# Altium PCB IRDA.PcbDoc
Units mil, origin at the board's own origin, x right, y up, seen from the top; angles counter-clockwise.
Board outline 3020 x 2198 mil, 4 copper layers (Top Layer, PwrPlane, GndPlane, Bottom Layer); 52 components, 34 nets, 373 pads, 123 vias.
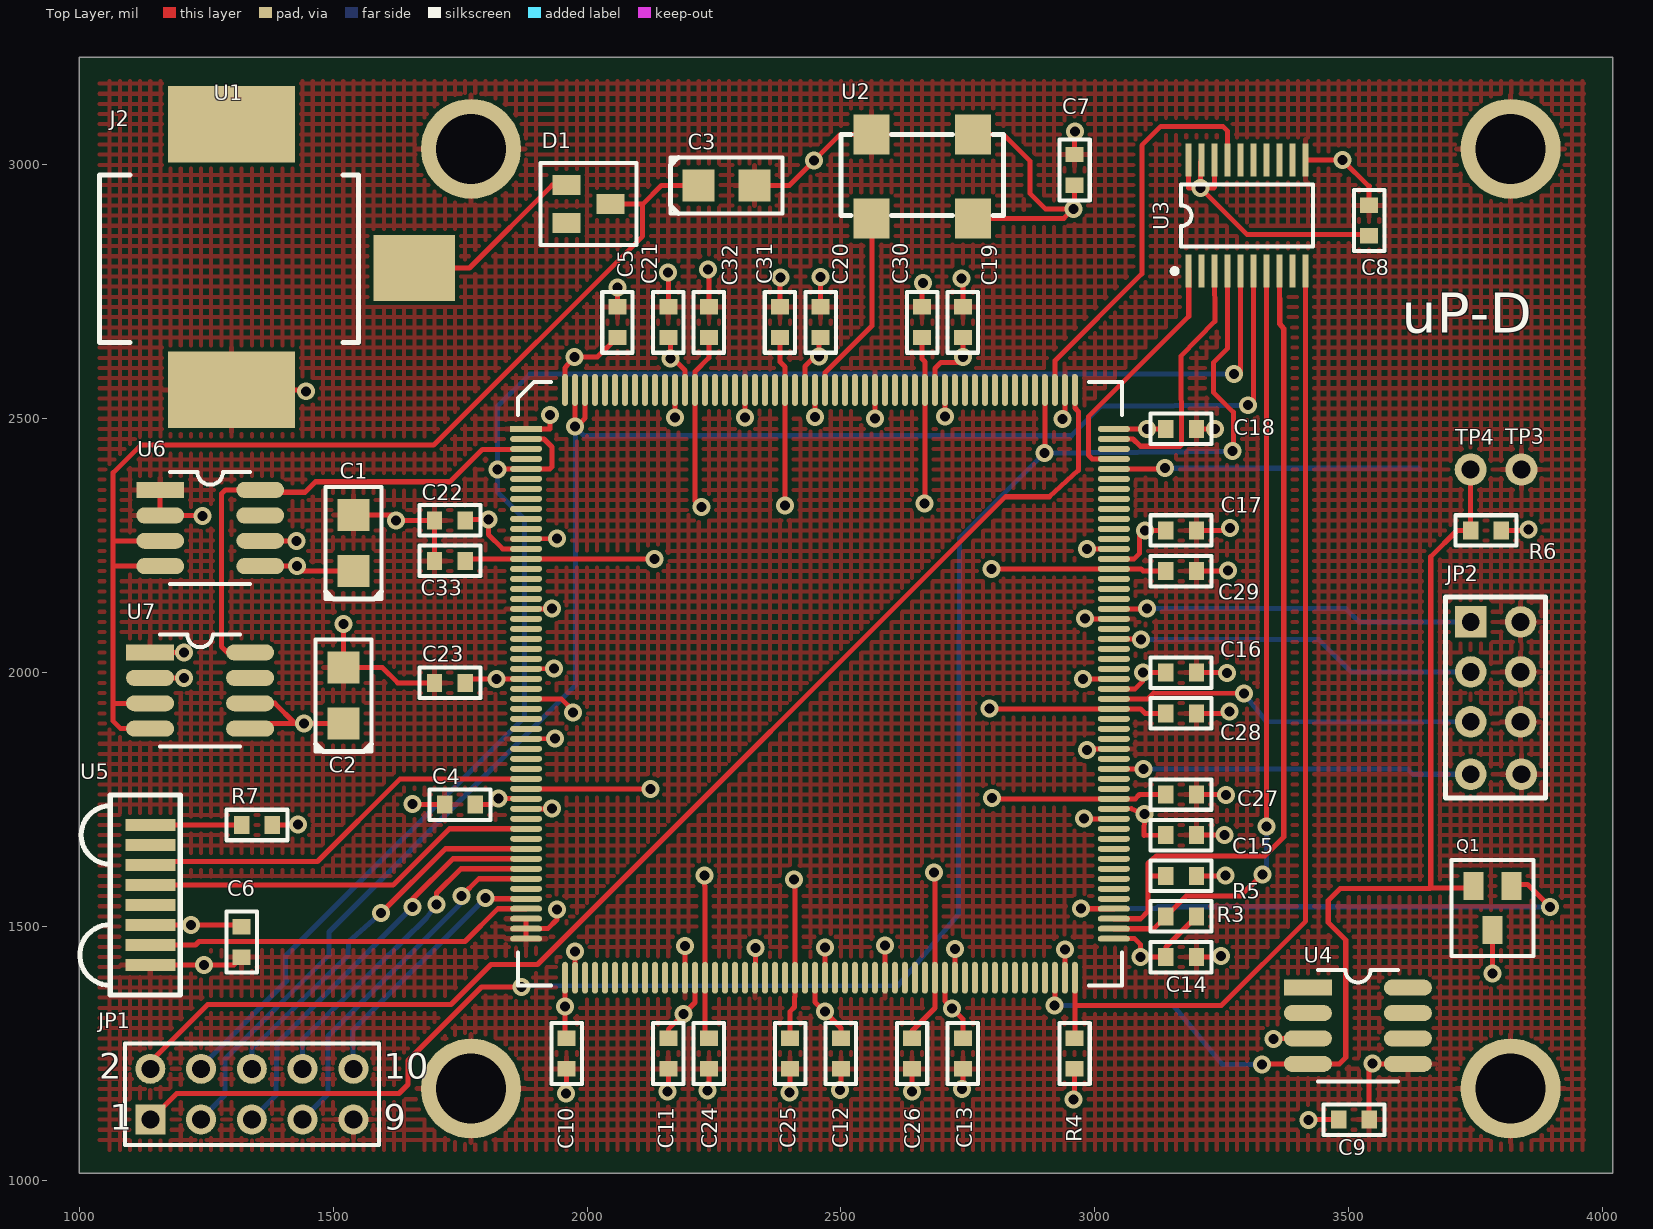
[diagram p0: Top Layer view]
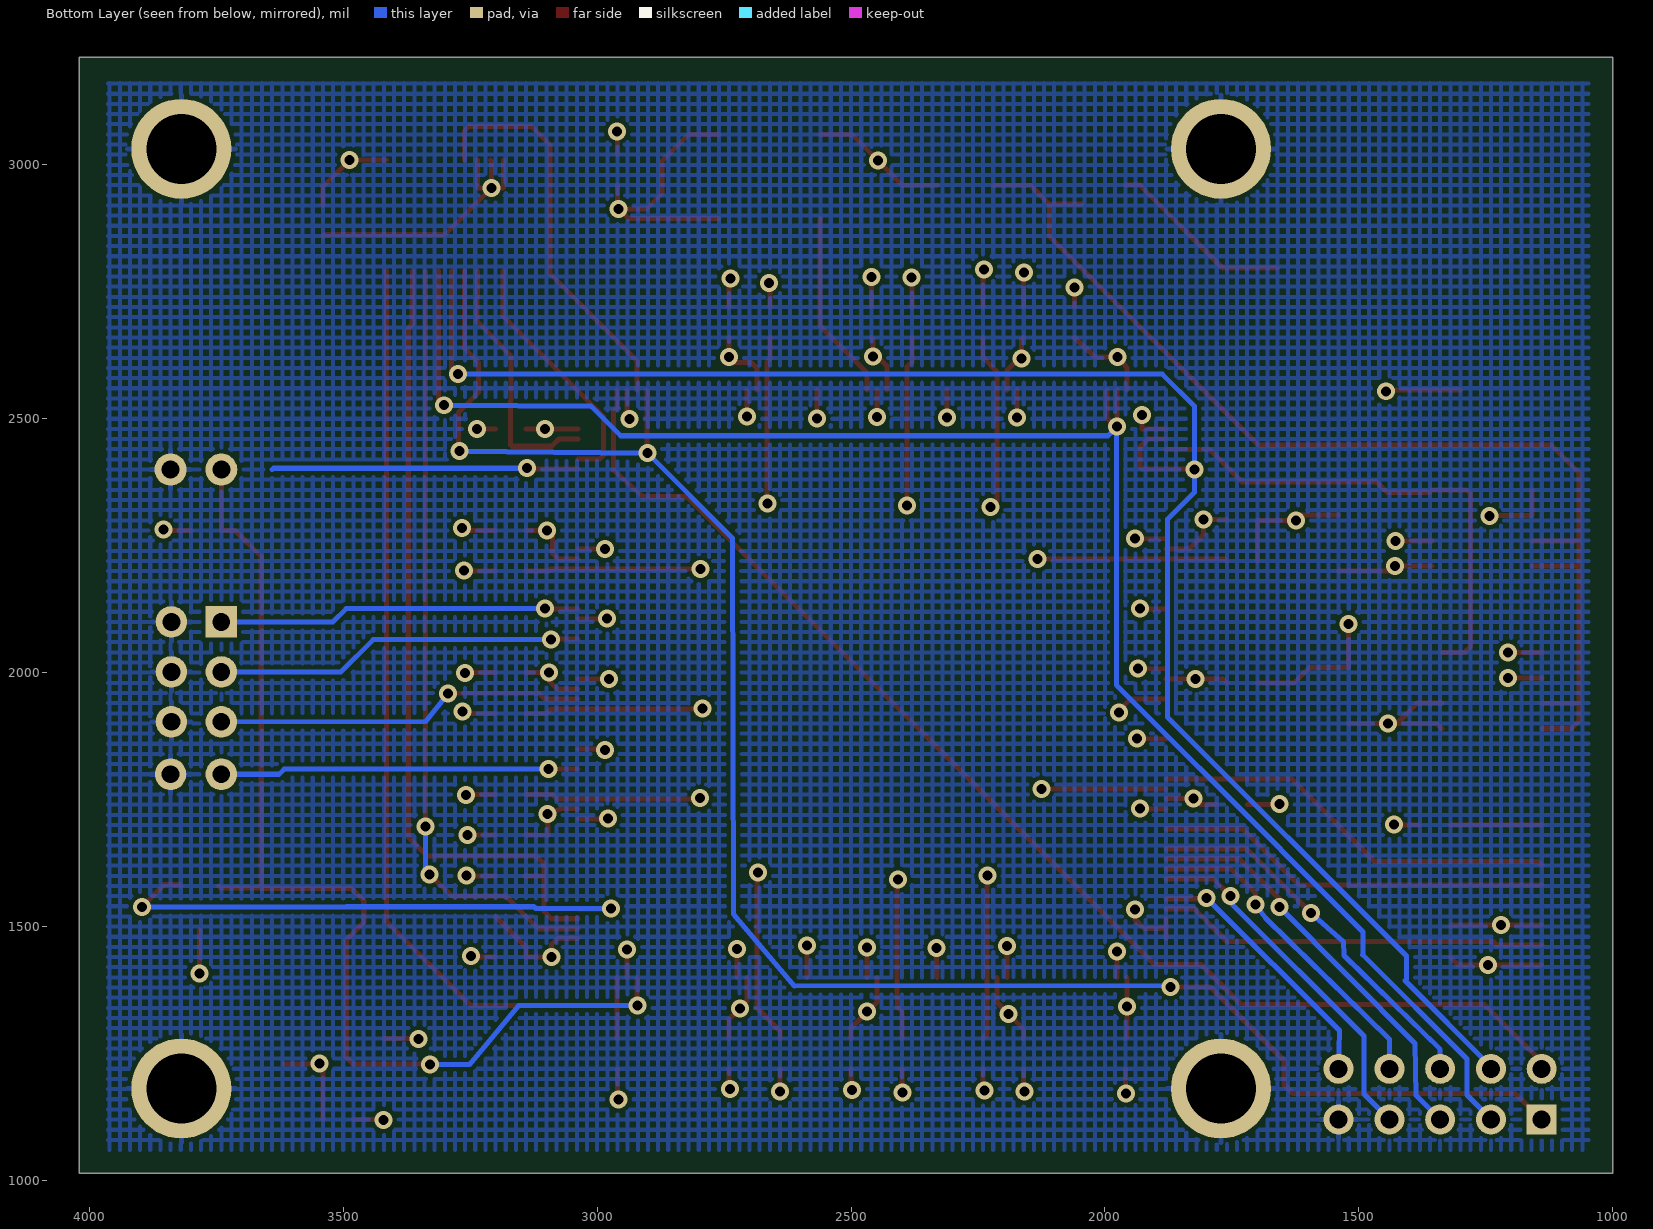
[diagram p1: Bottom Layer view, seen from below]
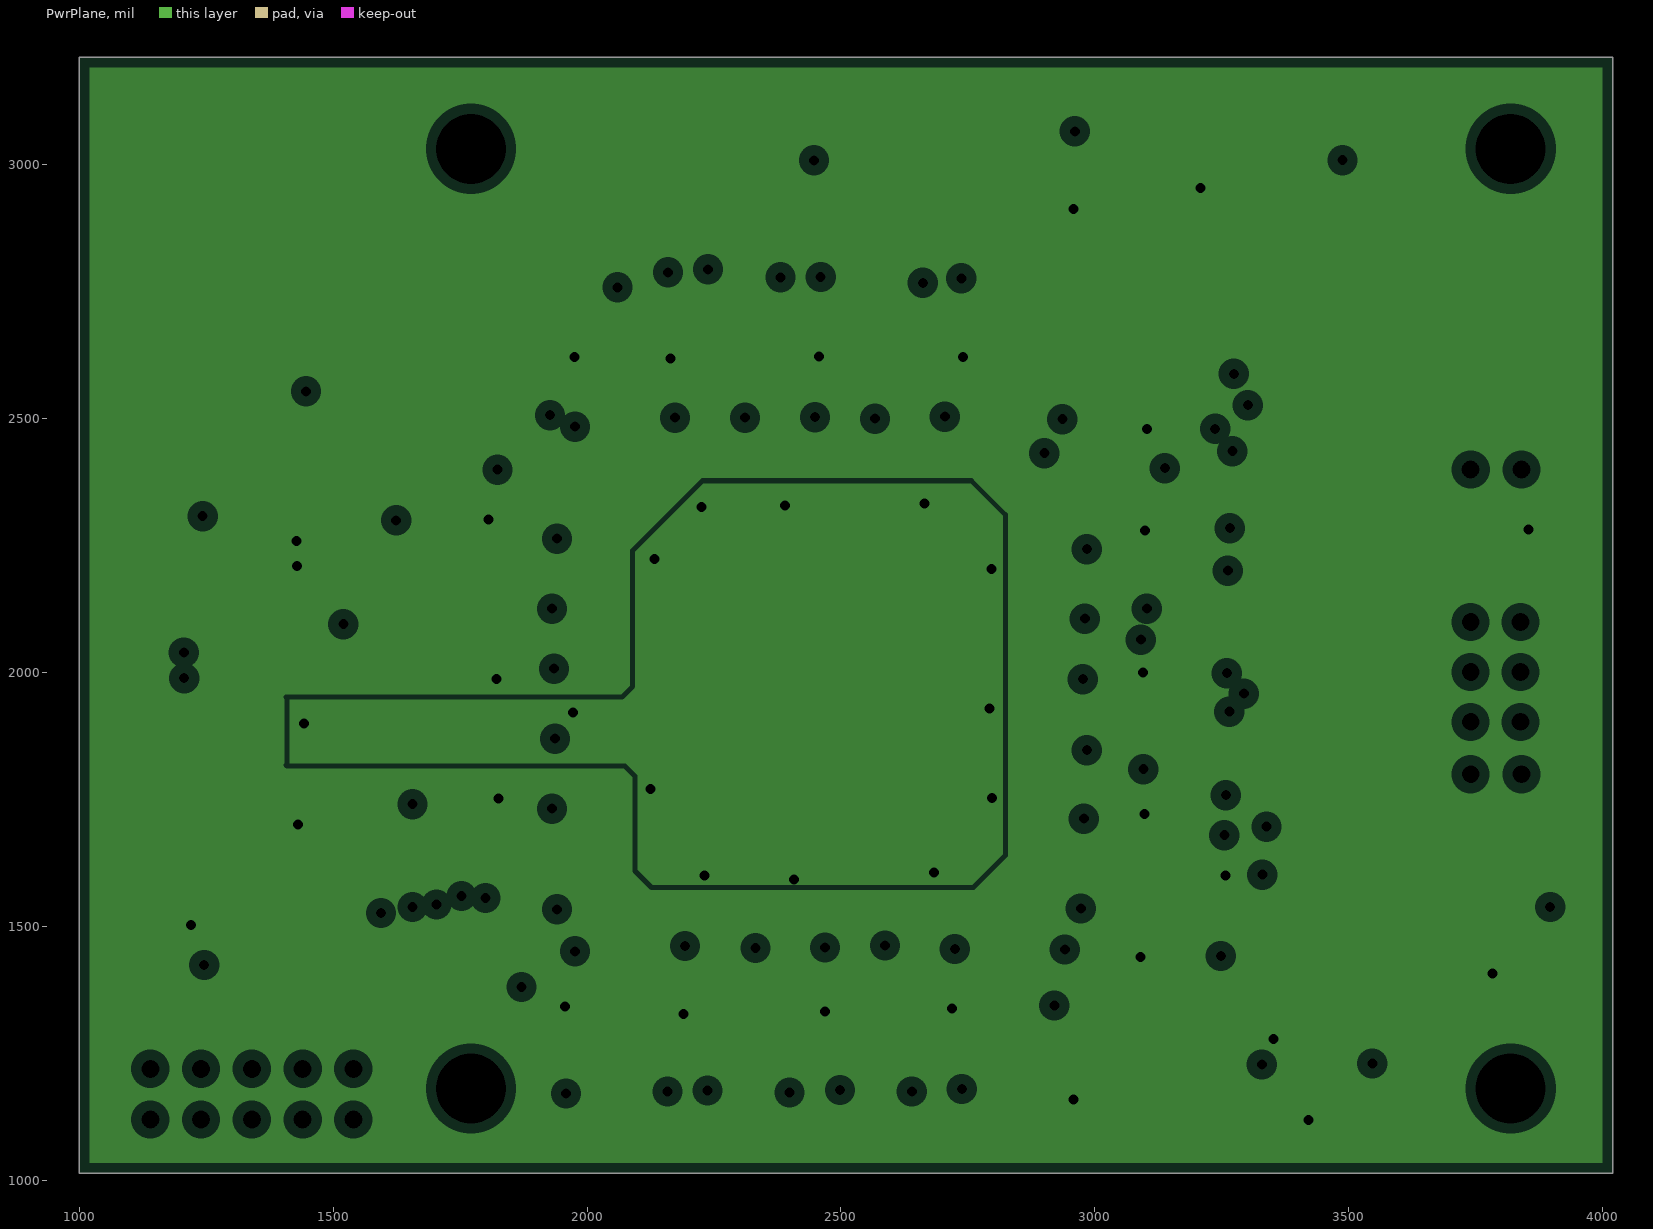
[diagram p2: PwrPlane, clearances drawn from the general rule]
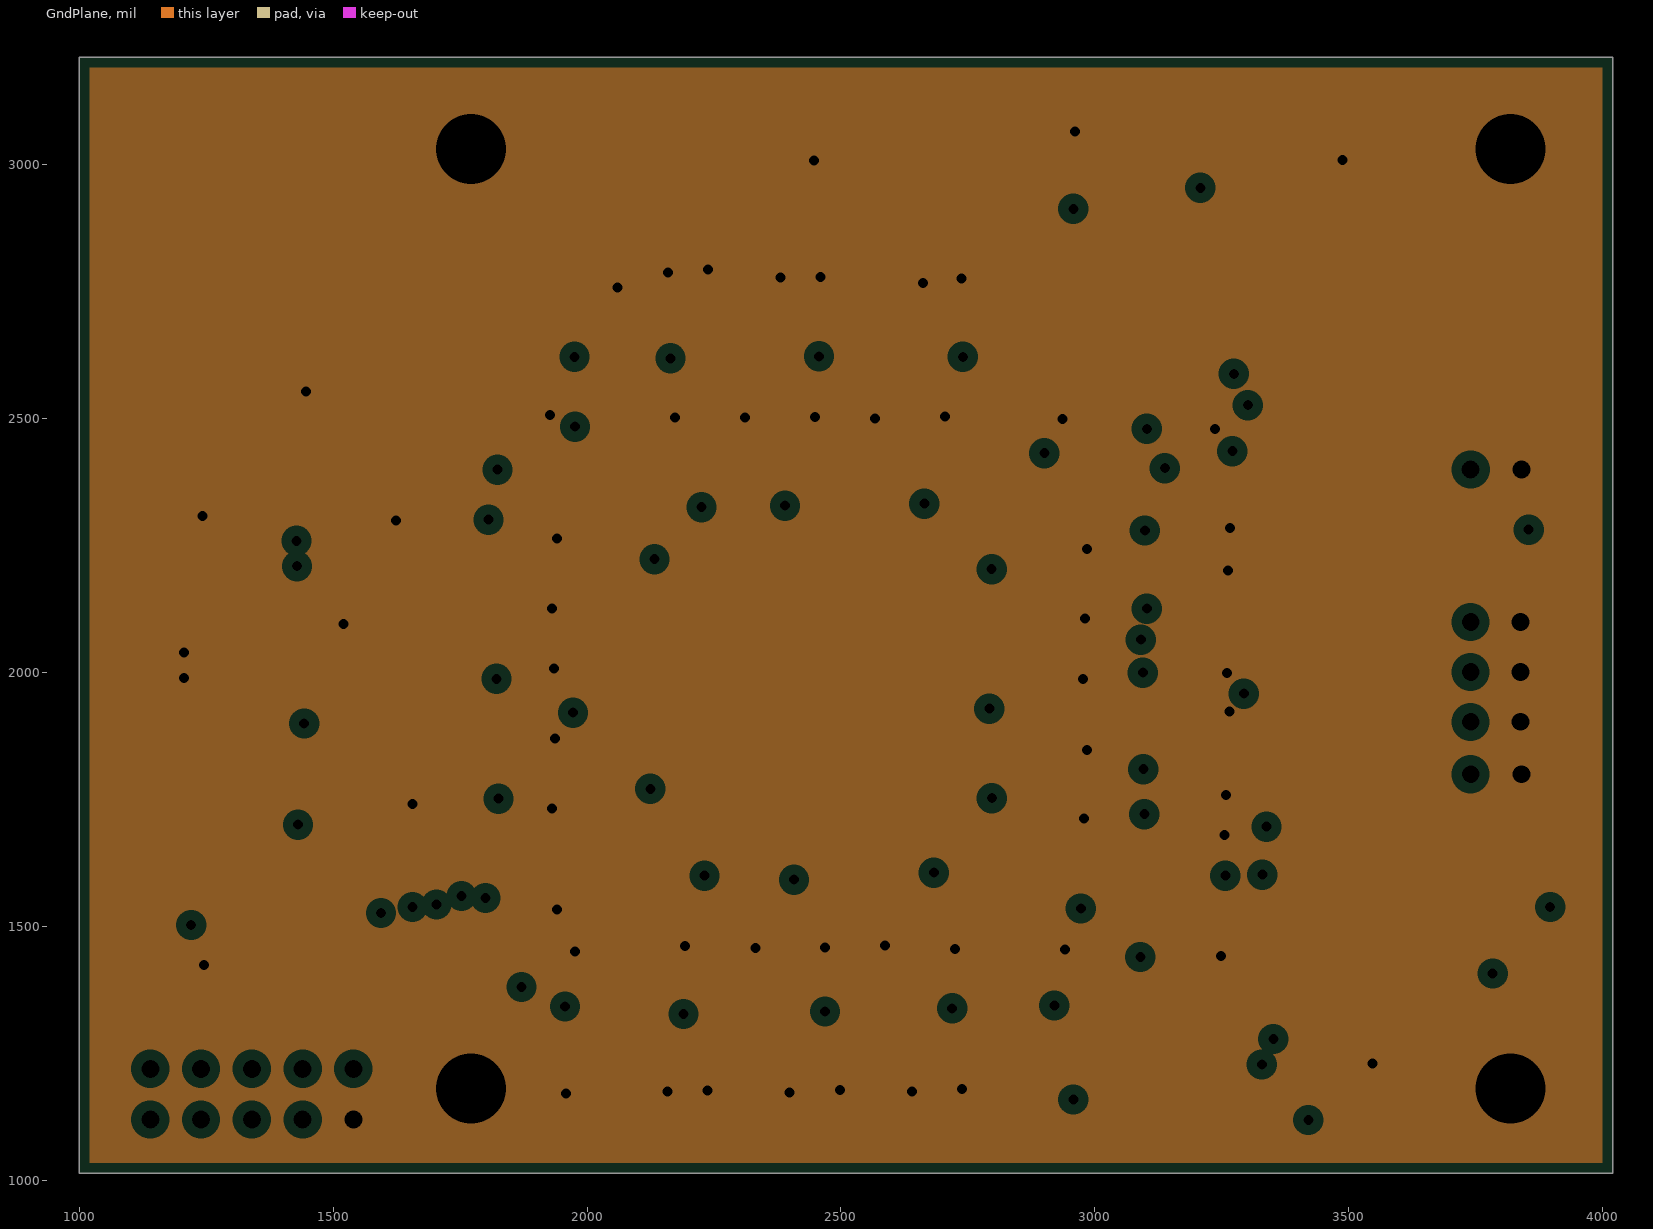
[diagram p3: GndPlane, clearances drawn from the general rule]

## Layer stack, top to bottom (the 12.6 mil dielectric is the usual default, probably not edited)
Top Layer: signal copper 1.4
Dielectric: core 12.6, FR-4, Dk 4.8
PwrPlane: plane copper 1.4, net (Multiple Nets)
Dielectric: prepreg 12.6, FR-4, Dk 4.8
GndPlane: plane copper 1.4, net GND
Dielectric: core 12.6, FR-4, Dk 4.8
Bottom Layer: signal copper 1.4

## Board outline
1000,1014 4020,1014 4020,3212 1000,3212

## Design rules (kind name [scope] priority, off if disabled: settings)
Clearance ClearanceQ [(HasFootprint('QFP208')) vs (HasFootprint('QFP208'))] p1: gap=7 // QP208
Clearance clearance [All] p2: gap=7.87 // general
FabricationTestPointUsage TestPointUsage [All] p1: valid=0 allowmultiple=FALSE
FabricationTestpoint Testpoint [All] p1: side=3 testpointundercomponent=TRUE minsize=40 maxsize=100 preferedsize=60 minholesize=0 maxholesize=40 preferedholesize=32 testpointgrid=1 allowsidetop=TRUE allowsidebottom=TRUE usegrid=TRUE gridtolerance=0.01
HoleSize [All] p1: absolutevalues=TRUE maxlimit=157.48 minlimit=1 maxpercent=80.000 minpercent=20.000
PlaneClearance [All] p1: clearance=20
PlaneConnect [All] p1: planeconnectstyle=Relief reliefexpansion=20 reliefentries=4 reliefconductorwidth=10 reliefairgap=10
PolygonConnect [All] p1: connectstyle=Relief reliefconductorwidth=10 reliefentries=4 polygonreliefangle="90 Angle"
RoomDefinition U_IrPwr [InComponentClass('U_IrPwr')] p1: confinementstyle=ConfineOut formatcopy=TRUE lockcomponents=FALSE outline 997,1015 4021,1015 4021,3210 997,3210
RoomDefinition U_IrIO [InComponentClass('U_IrIO')] p2: confinementstyle=ConfineOut formatcopy=TRUE lockcomponents=FALSE outline 997,1015 4021,1015 4021,3210 997,3210
RoomDefinition TopPCB [InComponentClass('TopPCB')] p3: confinementstyle=ConfineOut formatcopy=TRUE lockcomponents=FALSE outline 1011,1011 4021,1011 4021,3210 1011,3210
RoutingVias [All] p1: holewidth=19.68 width=35.43 viastyle="Through Hole" minholewidth=19.68 minwidth=35.43 maxholewidth=19.68 maxwidth=35.43
SilkscreenOverComponentPads [All] p1: minsilkscreentomaskgap=10
SolderMaskExpansion [All] p1: expansion=4
Width Width_P [(InNet('VCC') OR InNet('GND') OR InNet('NOM5V') OR InNet('NOM6V') OR InNet('VCORE'))] p1: maxlimit=100 minlimit=7.87 preferedwidth=9.84
Width [All] p2: maxlimit=10 minlimit=9.84 preferedwidth=10
22 further rules are at their usual default settings.

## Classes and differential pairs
component class U_IO: JP1 JP2 Q1 R6 R7 TP3 TP4 U2 U4 U5
component class FPGA: R3 R4 R5 U3
component class pwr: C1 C2 C3 C4 C5 C6 C7 C8 C9 C10 C11 C12 C13 C14 C15 C16 C17 C18 C19 C20 C21 C22 C23 C24 C25 C26 C27 C28 C29 C30 C31 C32 C33 D1 J2 U6 U7
component class U_FPGA_U1_Auto: U1

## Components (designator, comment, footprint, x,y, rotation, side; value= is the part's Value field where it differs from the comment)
C1 "10uF" 3216POL 1540,2200 r90 top
C2 "10uF" 3216POL 1520,1900 r90 top
C3 "22uF" 3216POL 2220,2960 r0 top
C4 "100nF" M0603 1780,1740 r180 top
C5 "10nF" M0603 2060,2660 r90 top
C6 "100nF" M0603 1320,1500 r270 top
C7 "100nF" M0603 2960,2960 r90 top
C8 "100nF" M0603 3540,2860 r90 top
C9 "100nF" M0603 3480,1120 r0 top
C10 "10nF" M0603 1960,1280 r270 top
C11 "100nF" M0603 2160,1280 r270 top
C12 "10nF" M0603 2500,1280 r270 top
C13 "100nF" M0603 2740,1280 r270 top
C14 "10nF" M0603 3140,1440 r0 top
C15 "100nF" M0603 3140,1680 r0 top
C16 "10nF" M0603 3140,2000 r0 top
C17 "100nF" M0603 3140,2280 r0 top
C18 "10nF" M0603 3140,2480 r0 top
C19 "100nF" M0603 2740,2660 r90 top
C20 "10nF" M0603 2460,2660 r90 top
C21 "100nF" M0603 2160,2660 r90 top
C22 "100nF" M0603 1760,2300 r180 top
C23 "10nF" M0603 1760,1980 r180 top
C24 "100nF" M0603 2240,1280 r270 top
C25 "10nF" M0603 2400,1280 r270 top
C26 "100nF" M0603 2640,1280 r270 top
C27 "10nF" M0603 3140,1760 r0 top
C28 "100nF" M0603 3140,1920 r0 top
C29 "10nF" M0603 3140,2200 r0 top
C30 "100nF" M0603 2660,2660 r90 top
C31 "10nF" M0603 2380,2660 r90 top
C32 "100nF" M0603 2240,2660 r90 top
C33 "100nF" M0603 1760,2220 r180 top
D1 "*" SOT23 1960,2960 r270 top
J2 "*" DC-SOCKET 1300,3080 r270 top
JP1 "Header 5X2" HDR2X5 1140,1120 r0 top
JP2 "HDR4X2" HDR4X2 3740,2100 r270 top
Q1 "BSN20" SOT23 3820,1580 r180 top
R3 "4k7" M0603 3140,1520 r0 top
R4 "4k7" M0603 2960,1280 r270 top
R5 "4k7" M0603 3140,1600 r0 top
R6 "4k7" M0603 3740,2280 r0 top
R7 "10R" M0603 1320,1700 r0 top
TP3 "TP" TP 3740,2400 r90 top locked
TP4 "TP" TP 3840,2400 r90 top locked
U1 "XC2S300E-6PQ208C" QFP208 1880,2480 r0 top
U2 "XCO" QSMO-4200 2760,3060 r270 top
U3 "XCF02SVO20C" VO20 3300,2900 r0 top
U4 "DS18S20Z" SO8 3420,1380 r0 top
U5 "TFDU4100" TDFU4100 1140,1700 r270 top
U6 "TPS77533D" SO8 1160,2360 r0 top
U7 "TPS77518D" SO8 1140,2040 r0 top

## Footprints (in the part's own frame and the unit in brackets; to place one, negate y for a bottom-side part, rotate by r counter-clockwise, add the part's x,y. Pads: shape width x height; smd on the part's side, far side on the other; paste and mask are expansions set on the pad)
3216POL [mm]
  rect 1.6x1.6 smd: 1(-0.002,-0.01) 2(2.798,-0.01)
  silkscreen extent -1.4,-1.41 4.2,1.39
DC-SOCKET [mil]
  rect 150x250 smd: 1(523,0) 2(0,0)
  rect 130x160 smd: 3(283,360)
  silkscreen extent 100,-260 430,250
HDR2X5 [mm]
  rect 1.5x1.5 hole 0.9: 1(0,0)
  round 1.5 hole 0.9: 2(0,2.54) 3(2.54,0) 4(2.54,2.54) 5(5.08,0) 6(5.08,2.54) 7(7.62,0) 8(7.62,2.54) 9(10.16,0) 10(10.16,2.54)
  silkscreen extent -1.27,-1.27 11.43,3.81
HDR4X2 [mil]
  rect 62x62 hole 35: 1(0,0)
  round 62 hole 35: 2(0,98.43) 3(98.42,0) 4(98.42,98.43) 5(196.85,0) 6(196.85,98.43) 7(300,0) 8(300,100)
  silkscreen extent -49,-49 346,148
M0603 [mm]
  rect 0.77x0.9 smd: 1(0,0) 2(1.53,0)
  silkscreen extent -0.76,-0.76 2.29,0.76
QFP208 [mm]
  rect 1.6x0.3 smd: 1(0,0)
  oval 1.6x0.3 smd: 2(0,-0.5) 3(0,-1) 4(0,-1.5) 5(0,-2) 6(0,-2.5) 7(0,-3) 8(0,-3.5) 9(0,-4) 10(0,-4.5) 11(0,-5) 12(0,-5.5) 13(0,-6) 14(0,-6.5) 15(0,-7) 16(0,-7.5) 17(0,-8) 18(0,-8.5) 19(0,-9) 20(0,-9.5) 21(0,-10) 22(0,-10.5) 23(0,-11) 24(0,-11.5) 25(0,-12) 26(0,-12.5) 27(0,-13) 28(0,-13.5) 29(0,-14) 30(0,-14.5) 31(0,-15) 32(0,-15.5) 33(0,-16) 34(0,-16.5) 35(0,-17) 36(0,-17.5) 37(0,-18) 38(0,-18.5) 39(0,-19) 40(0,-19.5) 41(0,-20) 42(0,-20.5) 43(0,-21) 44(0,-21.5) 45(0,-22) 46(0,-22.5) 47(0,-23) 48(0,-23.5) 49(0,-24) 50(0,-24.5) 51(0,-25) 52(0,-25.5) 105(29.4,-25.5) 106(29.4,-25) 107(29.4,-24.5) 108(29.4,-24) 109(29.4,-23.5) 110(29.4,-23) 111(29.4,-22.5) 112(29.4,-22) 113(29.4,-21.5) 114(29.4,-21) 115(29.4,-20.5) 116(29.4,-20) 117(29.4,-19.5) 118(29.4,-19) 119(29.4,-18.5) 120(29.4,-18) 121(29.4,-17.5) 122(29.4,-17) 123(29.4,-16.5) 124(29.4,-16) 125(29.4,-15.5) 126(29.4,-15) 127(29.4,-14.5) 128(29.4,-14) 129(29.4,-13.5) 130(29.4,-13) 131(29.4,-12.5) 132(29.4,-12) 133(29.4,-11.5) 134(29.4,-11) 135(29.4,-10.5) 136(29.4,-10) 137(29.4,-9.5) 138(29.4,-9) 139(29.4,-8.5) 140(29.4,-8) 141(29.4,-7.5) 142(29.4,-7) 143(29.4,-6.5) 144(29.4,-6) 145(29.4,-5.5) 146(29.4,-5) 147(29.4,-4.5) 148(29.4,-4) 149(29.4,-3.5) 150(29.4,-3) 151(29.4,-2.5) 152(29.4,-2) 153(29.4,-1.5) 154(29.4,-1) 155(29.4,-0.5) 156(29.4,0)
  oval 0.3x1.6 smd: 53(1.95,-27.45) 54(2.45,-27.45) 55(2.95,-27.45) 56(3.45,-27.45) 57(3.95,-27.45) 58(4.45,-27.45) 59(4.95,-27.45) 60(5.45,-27.45) 61(5.95,-27.45) 62(6.45,-27.45) 63(6.95,-27.45) 64(7.45,-27.45) 65(7.95,-27.45) 66(8.45,-27.45) 67(8.95,-27.45) 68(9.45,-27.45) 69(9.95,-27.45) 70(10.45,-27.45) 71(10.95,-27.45) 72(11.45,-27.45) 73(11.95,-27.45) 74(12.45,-27.45) 75(12.95,-27.45) 76(13.45,-27.45) 77(13.95,-27.45) 78(14.45,-27.45) 79(14.95,-27.45) 80(15.45,-27.45) 81(15.95,-27.45) 82(16.45,-27.45) 83(16.95,-27.45) 84(17.45,-27.45) 85(17.95,-27.45) 86(18.45,-27.45) 87(18.95,-27.45) 88(19.45,-27.45) 89(19.95,-27.45) 90(20.45,-27.45) 91(20.95,-27.45) 92(21.45,-27.45) 93(21.95,-27.45) 94(22.45,-27.45) 95(22.95,-27.45) 96(23.45,-27.45) 97(23.95,-27.45) 98(24.45,-27.45) 99(24.95,-27.45) 100(25.45,-27.45) 101(25.95,-27.45) 102(26.45,-27.45) 103(26.95,-27.45) 104(27.45,-27.45) 157(27.45,1.95) 158(26.95,1.95) 159(26.45,1.95) 160(25.95,1.95) 161(25.45,1.95) 162(24.95,1.95) 163(24.45,1.95) 164(23.95,1.95) 165(23.45,1.95) 166(22.95,1.95) 167(22.45,1.95) 168(21.95,1.95) 169(21.45,1.95) 170(20.95,1.95) 171(20.45,1.95) 172(19.95,1.95) 173(19.45,1.95) 174(18.95,1.95) 175(18.45,1.95) 176(17.95,1.95) 177(17.45,1.95) 178(16.95,1.95) 179(16.45,1.95) 180(15.95,1.95) 181(15.45,1.95) 182(14.95,1.95) 183(14.45,1.95) 184(13.95,1.95) 185(13.45,1.95) 186(12.95,1.95) 187(12.45,1.95) 188(11.95,1.95) 189(11.45,1.95) 190(10.95,1.95) 191(10.45,1.95) 192(9.95,1.95) 193(9.45,1.95) 194(8.95,1.95) 195(8.45,1.95) 196(7.95,1.95) 197(7.45,1.95) 198(6.95,1.95) 199(6.45,1.95) 200(5.95,1.95) 201(5.45,1.95) 202(4.95,1.95) 203(4.45,1.95) 204(3.95,1.95) 205(3.45,1.95) 206(2.95,1.95) 207(2.45,1.95) 208(1.95,1.95)
  silkscreen extent -0.4,-27.85 29.8,2.35
QSMO-4200 [mm]
  rect 2x1.8 smd: 1(0,0) 2(0,-5.08) 3(4.2,-5.08) 4(4.2,0)
  silkscreen extent 0,-6.6 4.06,1.52
SO8 [mm]
  rect 2.4x0.8 smd: 1(-0.008,-0.006)
  oval 2.4x0.8 smd: 2(-0.008,-1.276) 3(-0.008,-2.546) 4(-0.008,-3.816) 5(4.992,-3.816) 6(4.992,-2.546) 7(4.992,-1.276) 8(4.992,-0.006)
  silkscreen extent 0.49,-4.71 4.49,0.89
SOT23 [mm]
  rect 1x1.4 smd: 1(0,0) 2(0.95,2.2) 3(1.9,0)
  silkscreen extent -1.1,-1.3 3,3.5
TDFU4100 [mm] "IrDA Tranceiver"
  rect 0.6x2.5 smd: 1(0,0) 2(1,0) 3(2,0) 4(3,0) 5(4,0) 6(5,0) 7(6,0) 8(7,0)
  silkscreen extent -1.5,-3.52 8.5,1.5
TP [mm]
  round 1.6 hole 0.9: 1(0,0)
VO20 [mm] "20-Lead TSOP (VO20)"
  rect 0.3x1.65 smd: 1(-2.925,-2.775) 2(-2.275,-2.775) 3(-1.625,-2.775) 4(-0.975,-2.775) 5(-0.325,-2.775) 6(0.325,-2.775) 7(0.975,-2.775) 8(1.625,-2.775) 9(2.275,-2.775) 10(2.925,-2.775) 11(2.925,2.775) 12(2.275,2.775) 13(1.625,2.775) 14(0.975,2.775) 15(0.325,2.775) 16(-0.325,2.775) 17(-0.975,2.775) 18(-1.625,2.775) 19(-2.275,2.775) 20(-2.925,2.775)
  silkscreen extent -3.75,-2.9 3.3,1.55

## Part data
C1 C2 C3: library part CAPACITOR-POL, "ELECTROLYTIC/TANTALUM CAP"
C4 C5 C6 C7 C8 C9 C10 C11 C12 C13 C14 C15 C16 C17 C18 C19 C20 C21 C22 C23 C24 C25 C26 C27 C28 C29 C30 C31 C32 C33: library part CAP, "Cap 0603"
D1: library part DIODE, "DIODE"
J2: library part DC-SOCKET, "Switchcraft RASM712,Kycon KLD-SMT-0201"
JP1: "Header, 5-Pin, Dual row"
JP2: "HEADER 4X2 SQ PIN"
Q1: library part NMOSFET2
R3 R4 R5 R6 R7: library part RES, "SMT RESISTOR"
TP3 TP4: "SMALL PAD"
U1: "Spartan-IIE 1.8V FPGA, 208-Pin PQFP, Standard Performance, Commercial Grade"
U3: "XCF00S Series, Platform Flash In-System Programmable Configuration 3.3V PROM, 20-Pin TSOP, 2-Megabit, Commercial Grade"
U5: library part TDFU4100, "IrDA TxRx"
U6: library part TPS77518D, "LDO 1V8 500mA"
U7: "LDO 1V8 500mA"

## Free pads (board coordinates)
  round 196.85 hole 137.8: ""(1771.65,1181.1) ""(1771.65,3031.5) ""(3818.9,1181.1) ""(3818.9,3031.5)

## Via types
v1: diameter 35.43, hole 19.68, Top Layer to Bottom Layer, 123 vias

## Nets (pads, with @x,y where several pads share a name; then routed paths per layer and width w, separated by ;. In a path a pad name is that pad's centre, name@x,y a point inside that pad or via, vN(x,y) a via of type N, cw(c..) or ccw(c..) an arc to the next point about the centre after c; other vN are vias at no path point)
CC1: JP2.1 U1.138 | length 713.3
  Top Layer w10: U1.138 3087.28,2125.67 v1(3102.36,2125.98)
  Bottom Layer w10: v1(3102.36,2125.98) 3494.09,2125.98 3520.08,2100 JP2.1
CC2: JP2.3 U1.135 | length 729.5
  Top Layer w10: U1.135 3088.9,2066.61 v1(3090.55,2064.96)
  Bottom Layer w10: v1(3090.55,2064.96) 3440.95,2064.96 3504.33,2001.58 JP2.3
CC3: JP2.5 U1.129 | length 733.3
  Top Layer w10: U1.129 3104.02,1948.51 3115.16,1959.65 v1(3293.31,1958.66)
  Bottom Layer w10: v1(3293.31,1958.66) 3338.39,1903.54 JP2.5
CC4: JP2.7 U1.122 | length 707
  Top Layer w10: U1.122 3094.8,1810.71 v1(3095.47,1810.04)
  Bottom Layer w10: v1(3095.47,1810.04) 3616.14,1810.04 3626.18,1800 JP2.7
CCLK: U1.155 U3.3 | length 509.1
  Top Layer w10: U1.155 3075.34,2460.32 3089.79,2445.87 3167.32,2445.87 3170.28,2448.82 3169.29,2623.03 3236.22,2691.93 U3.3
CLK_BRD: U1.182 U2.3 | length 376.6
  Top Layer w10: U1.182 2468.58,2590.63 2561.02,2683.07 2561.02,2893.62 U2.3
DIN: U1.153 U3.1 | length 497.5
  Top Layer w10: U1.153 2994.76,2420.95 2987.2,2428.5 2987.2,2503.94 3184.84,2701.57 U3.1
DONE: R4.1 U1.104 U3.10 | length 1923
  Top Layer w10: R4.1 2960.71,1280.71 U1.104 ; 2960.71,1344.49 3249.02,1344.49 3415.16,1510.63 U3.10
DQ: Q1.3 R6.1 TP3.1 U1.102 U4.4 | length 2181.8
  Top Layer w10: v1(2920.28,1344.49) 2921.34,1361.14 U1.102 ; v1(3328.74,1228.35) 3330.14,1229.75 3481.72,1229.75 3494.09,1242.13 3494.09,1473.43 3459.65,1507.87 3459.65,1551.18 3483.27,1574.8 3660,1574.8 3661.42,1576.22 ; TP3.1 R6.1 3713.07,2280 3661.42,2228.35 3661.42,1576.22 ; Q1.3 3741.42,1576.22 3661.42,1576.22
  Bottom Layer w10: v1(2920.28,1344.49) 3154.53,1344.49 3250.98,1228.35 v1(3328.74,1228.35)
GND: C1.2 C2.2 C3.2 C4.2 C5.2 C6.2 C7.2 C8.2 C9.2 C10.2 C11.2 C12.2 C13.2 C14.2 C15.2 C16.2 C17.2 C18.2 C19.2 C20.2 C21.2 C22.2 C23.2 C24.2 C25.2 C26.2 C27.2 C28.2 C29.2 C30.2 C31.2 C32.2 C33.2 J2.1 JP1.9 JP2.2 JP2.4 JP2.6 JP2.8 pad. TP4.1 U1.1 U1.12 U1.19 U1.25 U1.32 U1.39 U1.50 U1.51 U1.52 U1.54 U1.65 U1.72 U1.79 U1.85 U1.92 U1.103 U1.117 U1.124 U1.131 U1.137 U1.144 U1.158 U1.170 U1.177 U1.183 U1.190 U1.197 U2.2 U3.11 U4.5 U5.8 U6.1 U6.2 U7.1 U7.2 | length 4546.4
  Top Layer w9.84: U7.2 1206.12,1989.75 v1(1206.69,1989.17) ; U7.1 v1(1206.09,2039.75) ; U5.8 1304.65,1424.41 C6.2 ; U6.1 U6.2 1241.43,2309.75 v1(1243.11,2308.07) ; J2.1 1443.98,2557 v1(1446.85,2554.13) ; v1(1520.15,2095.47) 1520.41,2095.73 C2.2 1597.13,2010.16 1627.28,1980 C23.2 ; C1.2 1614.06,2310.16 v1(1624.21,2300) C22.2 C33.2 ; v1(1656.5,1741.14) 1657.64,1740 C4.2 ; U1.52 U1.50 ; U1.39 1930.79,1731.97 v1(1931.1,1732.28) ; U1.32 v1(1937.01,1870.08) ; U1.25 v1(1935.04,2007.87) v1@1935.04,2006.89 ; U1.19 1930.79,2125.67 v1(1931.1,2125.98) ; U1.12 v1(1940.94,2263.78) v1@1940.94,2264.76 ; U1.1 1927.48,2480 v1(1927.17,2506.89) ; U1.51@1880.25,1496 1923,1496 1941,1514 v1(1941,1534) ; v1(1958.66,1171.26) 1960,1172.6 C10.2 ; U1.54 v1(1976.46,1451.18) ; C5.2 2060,2758.82 v1(2060.04,2758.86) ; v1(2158.46,1175.2) 2160,1176.73 C11.2 ; v1(2159.45,2788.39) 2160,2787.83 C21.2 ; v1(2173.23,2501.97) 2173.31,2513.86 U1.197 ; v1(2192.91,1461.61) U1.65 ; v1(2237.2,1177.17) 2240,1179.96 C24.2 ; v1(2238.19,2794.29) 2240,2792.48 C32.2 ; v1(2311.02,2501.97) 2311.1,2512.87 U1.190 ; C3.2 2398.57,2959.59 2498.98,3060 U2.2 ; U1.72 v1(2331.69,1457.68) ; C31.2 2380,2777.64 v1(2380.91,2778.54) ; v1(2398.62,1173.23) 2400,1174.61 C25.2 ; v1(2448.82,2502.95) U1.183 ; C20.2 v1(2460,2779.17) ; v1(2468.5,1458.66) U1.79 ; v1(2498.03,1178.15) 2500,1180.12 C12.2 ; v1(2566.93,2500) 2567.01,2507.95 U1.177 ; v1(2586.61,1462.6) U1.85 ; v1(2639.76,1175.2) 2640,1175.43 C26.2 ; C30.2 2660,2766.3 v1(2661.42,2767.72) ; v1(2704.72,2503.94) U1.170 ; v1(2724.41,1455.71) 2724.49,1447.76 U1.92 ; v1(2737.2,2776.57) 2740,2773.78 C19.2 ; v1(2738.19,1180.12) 2740,1181.93 C13.2 ; v1(2936.02,2499.02) 2941.02,2509.92 U1.158 ; v1(2940.94,1454.72) 2941.02,1440.87 U1.103 ; C7.2 2960,3065.32 v1(2960.63,3065.94) ; v1(2976.38,1987.2) 2988.86,1987.88 U1.131 ; v1(2978.35,1712.6) 2990.83,1712.29 U1.117 ; v1(2980.32,2106.3) 2991.46,2105.99 U1.137 ; v1(2984.25,1847.44) 2986.89,1850.08 U1.124 ; v1(2984.25,2243.11) 2993.78,2243.78 U1.144 ; C14.2 3246.1,1440 v1(3248.03,1441.93) ; C15.2 3254.8,1680 v1(3254.92,1680.12) ; C27.2 3256.73,1760 v1(3257.87,1758.86) ; C28.2 3261.54,1920 v1(3264.76,1923.23) ; C16.2 3258.86,2000 v1(3259.84,1999.02) ; C29.2 3261.02,2200 v1(3261.81,2200.79) ; C17.2 3261.3,2280 v1(3265.75,2284.45) ; C18.2 v1(3236.89,2480) ; U3.11 v1(3487.8,3009.25) 3538.39,2958.66 3540.35,2958.66 ; C8.2 3540,2958.31 ; C9.2 3540.24,1224.29 v1(3546.26,1230.32) 3546.83,1229.75 U4.5
  other v1: 1246.06,1424.41 2446.85,3008.86
INIT: R5.1 U1.107 U3.8 | length 1611.8
  Top Layer w10: U1.107@3037.79,1515.75 U1.107 3090.24,1515.43 3104.33,1529.53 3104.33,1624.02 3121.06,1638.78 3334.65,1638.78 3372.05,1676.18 3372.05,2677.17 3364.17,2687.01 U3.8 ; 3104.33,1599.41 3112.8,1600 R5.1@3142.32,1600
IRRX: U1.41 U5.4 | length 785.9
  Top Layer w10: U5.4 1618.31,1581.89 1729.02,1692.6 U1.41
IRSC: U1.49 U5.7 | length 769.6
  Top Layer w10: U5.7 1229.13,1463.78 1235.83,1470.47 1759.84,1470.47 1824.49,1535.12 U1.49
IRTX: U1.36 U5.3 | length 810.3
  Top Layer w10: U5.3 1147.05,1628.31 1469.49,1628.31 1632.2,1791.03 U1.36
JTAG_NEXUS_TCK: JP1.7 U1.46 | length 711.7
  Top Layer w10: JP1.7 JP1.7@1440.87,1120 ; v1(1752.95,1560.04) 1787.09,1594.17 U1.46
  Bottom Layer w10: JP1.7 1490.16,1170.16 1490.16,1284.31 1752.95,1547.11 v1(1752.95,1560.04)
JTAG_NEXUS_TDI: JP1.5 U1.44 | length 824.7
  Top Layer w10: JP1.5 JP1.5@1340,1124.45 ; v1(1656.5,1538.39) 1656.5,1554.13 1735.91,1633.55 U1.44
  Bottom Layer w10: JP1.5 1387.8,1167.8 1389.76,1269.68 v1(1656.5,1538.39)
JTAG_NEXUS_TDO: 
JTAG_NEXUS_TMS: JP1.8 U1.45 | length 652.8
  Top Layer w10: JP1.8@1438.98,1221.02 JP1.8 ; v1(1703.74,1543.31) 1703.74,1565.94 1751.66,1613.86 U1.45
  Bottom Layer w10: JP1.8 1440,1278.58 1684.06,1516.73 v1(1703.74,1543.31)
NetJP1_6: JP1.6 U1.43 | length 753.5
  Top Layer w10: v1(1594.49,1526.57) 1721.14,1653.23 U1.43
  Bottom Layer w10: JP1.6 1340,1258.31 1529.53,1442.91 1530.51,1470.47 v1(1594.49,1526.57)
NetJP1_10: JP1.10 U1.48 | length 527.5
  Top Layer w10: JP1.10@1538.39,1221.61 JP1.10 ; v1(1800.2,1556.1) 1801.49,1554.81 U1.48
  Bottom Layer w10: JP1.10 1538.39,1295.28 v1(1800.2,1556.1)
NetR7_1: R7.1 U5.1 | length 180
  Top Layer w10: U5.1 R7.1
NOM5V: C3.1 D1.2 U6.3 U6.4 U7.3 U7.4 | length 2316
  Top Layer w9.84: 1066.93,1937.01 1069.67,1939.75 U7.3 ; 1066.93,2207.68 1069,2209.75 U6.4 ; 1066.93,2260.83 1068.01,2259.75 U6.3 ; U7.4 1081.71,1889.75 1066.93,1904.53 1066.93,2393.7 1121.06,2447.83 1697.83,2447.83 2109.61,2859.61 2109.61,2922.6 ; D1.2 2109.61,2922.6 ; C3.1 2146.6,2959.59 2109.61,2922.6
NOM6V: D1.1 J2.3 | length 367.5
  Top Layer w9.84: J2.3 1768.46,2797 1931.46,2960 D1.1
PROGRAM: R3.1 U1.106 U3.7 | length 1537.8
  Top Layer w10: U1.106 3115.75,1495.75 3180.04,1560.04 3286.42,1560.04 v1(3329.72,1602.36) v1@3335.63,1609.25 ; v1(3338.19,1696.85) 3338.39,1696.65 U3.7
  Bottom Layer w10: v1(3329.72,1602.36) 3338.39,1610.04 v1@3338.39,1696.65
RESET_N: U1.3 U6.8 U7.8 | length 1001.6
  Top Layer w10: U7.8 1291.94,2039.75 1280.51,2051.18 1280.51,2352.36 1287.9,2359.75 U6.8 1360.95,2355.32 1444.88,2355.32 1465.55,2375.98 1730.32,2375.98 1794.18,2439.85 1879.22,2439.85 U1.3
SPU_DQ: Q1.1 U1.108 | length 1086.8
  Top Layer w10: v1@2972.75,1535.12 U1.108 ; Q1.1 3822.68,1582.68 3852.36,1582.68 v1(3896.65,1538.39)
  Bottom Layer w10: v1(2972.44,1535.43) 3119.43,1535.43 3120.12,1536.11 3121.14,1536.11 3124.05,1539.03 3493.15,1539.03 3493.79,1538.39 v1(3896.65,1538.39)
TCK: JP1.3 U1.206 U1.207 U3.6 | length 3455.6
  Top Layer w10: U1.207 1976.38,2556.69 v1(1976.38,2484.25) 1979.33,2484.25 1996.14,2501.06 U1.206 ; v1(3301.18,2526.57) 3312.8,2526.38 U3.6
  Bottom Layer w10: JP1.3 1240,1120.91 1287.4,1168.31 1287.4,1239.17 1492.62,1444.39 ; 1492.13,1444.88 1492.13,1489.17 1653.54,1650.59 1653.54,1651.57 1977.36,1975.39 v1@1977.36,2483.27 ; v1(1976.38,2484.25) 1994.09,2466.54 2953.74,2466.54 3011.81,2524.61 v1(3301.18,2526.57)
TDI: U1.159 U3.17 | length 798
  Top Layer w10: U1.159 2921.34,2614.25 3092.52,2785.43 3092.52,3038.39 3129.92,3075.79 3251.97,3075.79 3261.61,3066.14 U3.17
TDIH: JP1.1 U1.160 U3.4 | length 3658.7
  Top Layer w10: JP1.1 1140.67,1120 1191.93,1171.26 1629.92,1171.26 1647.64,1188.98 1647.64,1236.22 1792.32,1380.91 v1(1871.06,1380.91) ; v1(2900.59,2432.09) 2901.65,2433.15 U1.160 ; v1@3261.61,2434.84 v1(3270.67,2436.02) 3272.64,2437.99 3272.64,2512.8 3233.27,2552.17 3233.27,2610.24 3261.61,2638.58 U3.4
  Bottom Layer w10: v1(1871.06,1380.91) 1874.02,1383.86 2611.22,1382.87 2731.3,1524.61 2733.27,2264.76 v1(2900.59,2432.09) v1(3270.67,2436.02)
TDO: JP1.2 U1.157 | length 2483.2
  Top Layer w10: JP1.2 1140,1233.5 1252.95,1346.46 1732.42,1346.46 1811.16,1425.2 1902.56,1425.2 2823.82,2346.46 2910.43,2346.46 2967.52,2398.62 2967.52,2514.49 2960.71,2521.3 U1.157
TEST1: U1.152 | length 604.1
  Top Layer w10: U1.152 3136.5,2401.26 v1(3137.8,2402.56)
  Bottom Layer w10: v1(3137.8,2402.56) 3637.44,2402.56 3640,2400
TMS: JP1.4 U1.2 U1.5 U3.5 | length 3487.5
  Top Layer w10: v1(1823.82,2399.61) 1825.47,2401.26 1926.85,2401.26 1931.1,2405.51 1931.1,2444.32 1915.11,2460.32 U1.2 ; v1@3287.2,2587.8 U3.5
  Bottom Layer w10: JP1.4 1240,1224.25 1409.45,1393.7 ; 1406.5,1396.65 1406.5,1441.93 1876.97,1912.4 1876.97,2302.17 1823.82,2355.31 1823.82,2524.61 1887.01,2587.8 v1@3287.2,2587.8
  other v1: 3273.62,2588.58
VCCINT: C2.1 C24.1 C25.1 C26.1 C27.1 C28.1 C29.1 C30.1 C31.1 C32.1 C33.1 U1.14 U1.28 U1.37 U1.67 U1.76 U1.90 U1.119 U1.128 U1.142 U1.172 U1.186 U1.195 U7.5 U7.6 | length 4083.7
  Top Layer w9.84: C33.1 1764.1,2224.09 2132.2,2224.09 v1(2132.87,2223.43) ; U1.37 v1(2124.68,1771.34) ; U1.28 1949.49,1948.51 1972.44,1925.55 v1(1972.44,1921.26) ; v1(2225.39,2325.79) 2212.68,2338.5 2212.68,2592.6 2240,2619.92 C32.1 ; C31.1 2380,2612.13 2389.84,2602.28 2389.84,2328.82 v1(2389.76,2328.74) ; C25.1 2400,1333.27 2408.46,1341.73 ; C26.1 2640,1294.53 2685.12,1339.65 2685.12,1604.25 v1(2683.07,1606.3) ; C30.1 2660,2617.56 2665.43,2612.13 2665.43,2333.74 v1(2664.37,2332.68) ; v1(2792.32,1929.13) 2792.64,1928.82 3089.88,1928.82 3098.7,1920 C28.1 ; v1(2796.89,2203.74) 2797.56,2204.41 3090.87,2204.41 3095.28,2200 C29.1 ; v1(2797.24,1752.95) 2798.54,1751.65 3079.67,1751.65 3088.02,1760 C27.1
  Top Layer w10: U7.5 1346.69,1899.92 C2.1 ; U7.6 1385.25,1939.75 1425,1900 v1(1443,1900) v1@1443.08,1899.92 ; v1(2231.3,1600.39) 2231.3,1581.03 2232.36,1579.97 2232.36,1287.64 C24.1 ; v1(2407.48,1592.52) 2409.53,1590.47 2409.53,1361.98 2408.46,1360.91 2408.46,1341.73
VCCO: C1.1 C4.1 C5.1 C6.1 C7.1 C8.1 C9.1 C10.1 C11.1 C12.1 C13.1 C14.1 C15.1 C16.1 C17.1 C18.1 C19.1 C20.1 C21.1 C22.1 C23.1 Q1.2 R3.2 R4.2 R5.2 R6.2 R7.2 U1.13 U1.26 U1.38 U1.53 U1.66 U1.78 U1.91 U1.105 U1.118 U1.130 U1.143 U1.156 U1.171 U1.184 U1.196 U1.208 U2.1 U2.4 U3.18 U3.19 U3.20 U4.3 U5.6 U6.5 U6.6 | length 4267.9
  Top Layer w9.84: U5.6 1220.28,1503.15 v1(1220.47,1502.95) 1317.05,1502.95 C6.1 ; U6.5 1429.03,2209.75 1438.86,2199.92 C1.1 ; U6.6 v1(1428.15,2259.65) v1(1428.15,2259.65) ; R7.2 1430.32,1700 v1(1431.1,1700.79) ; C23.1 1767.88,1987.88 U1.26 ; C22.1 1761.18,2301.18 v1(1806.1,2301.18) 1806.1,2271.65 1833.98,2243.78 U1.13 ; C4.1 1811.85,1740 1823.82,1751.97 1879.69,1751.97 U1.38 ; U1.53 1956.77,1283.23 C10.1 ; U1.208 1956.77,2600.31 v1(1975.39,2622.05) 2020.67,2622.05 C5.1 ; C11.1 2160,1297.8 2212.68,1350.47 U1.66 ; C21.1 2164.37,2655.63 v1(2164.37,2619.09) 2174.21,2614.17 2192.99,2595.39 U1.196 ; U1.184 2429.21,2603.27 2441.1,2615.16 v1(2456.69,2623.03) 2456.69,2656.69 C20.1 ; U1.78 2448.9,1351.3 2500,1300.2 C12.1 ; U1.171 2685.12,2599.33 2697.01,2611.22 v1@2738.19,2611.22 ; U1.91 2704.8,1353.27 2740,1318.07 C13.1 ; v1@2740,2613.03 C19.1 ; U2.4 2938.94,2894.65 2960,2915.71 C7.1 ; U2.1 2819.84,3060 2872.05,3007.8 2872.05,2943.9 2902.56,2913.39 v1(2957.68,2913.39) ; v1(2957.68,1159.45) 2960,1161.77 R4.2 ; U1.105 3078.43,1476.07 3089.57,1464.93 v1(3089.57,1439.96) C14.1 ; U1.118 3071.85,1732.28 v1(3097.44,1721.46) 3096.46,1679.13 3126.1,1680 C15.1 ; U1.130 3079.41,1968.19 3093.5,1982.28 v1@3093.5,1999.02 ; U1.143 3077.44,2224.09 3087.6,2234.25 v1@3087.6,2277.56 ; U1.156 C18.1 ; v1(3094.49,2000) C16.1 ; v1(3098.43,2280) 3090.04,2280 C17.1 ; C14.1 C14.1 ; U3.20 3184.84,2955.51 3184.06,2954.72 3234.25,2954.72 3236.02,2956.5 U3.18 ; R3.2 3139.96,1459.72 C14.1 ; R5.2 3256.5,1600 v1(3256.89,1600.39) ; U3.19 3207.68,3006.5 v1(3207.68,2954.72) 3299.21,2863.19 3536.81,2863.19 C8.1 ; v1(3351.38,1278.54) 3352.58,1279.75 U4.3 ; v1(3420.28,1119.09) 3421.18,1120 C9.1 ; Q1.2 3782.6,1408.35 v1(3783.46,1407.48) ; R6.2 3852.83,2280 v1(3854.33,2281.5)
  other v1: 2190.14,1327.93 2468.5,1332.68 2719.05,1339.02 1956.77,1342.52 1825.79,1751.97 1821.85,1987.88 1429.13,2209.65 3102.36,2480 2740,2622.05
pads on no net: D1.3 J2.2 U1.4 U1.6 U1.7 U1.8 U1.9 U1.10 U1.11 U1.15 U1.16 U1.17 U1.18 U1.20 U1.21 U1.22 U1.23 U1.24 U1.27 U1.29 U1.30 U1.31 U1.33 U1.34 U1.35 U1.40 U1.42 U1.47 U1.55 U1.56 U1.57 U1.58 U1.59 U1.60 U1.61 U1.62 U1.63 U1.64 U1.68 U1.69 U1.70 U1.71 U1.73 U1.74 U1.75 U1.77 U1.80 U1.81 U1.82 U1.83 U1.84 U1.86 U1.87 U1.88 U1.89 U1.93 U1.94 U1.95 U1.96 U1.97 U1.98 U1.99 U1.100 U1.101 U1.109 U1.110 U1.111 U1.112 U1.113 U1.114 U1.115 U1.116 U1.120 U1.121 U1.123 U1.125 U1.126 U1.127 U1.132 U1.133 U1.134 U1.136 U1.139 U1.140 U1.141 U1.145 U1.146 U1.147 U1.148 U1.149 U1.150 U1.151 U1.154 U1.161 U1.162 U1.163 U1.164 U1.165 U1.166 U1.167 U1.168 U1.169 U1.173 U1.174 U1.175 U1.176 U1.178 U1.179 U1.180 U1.181 U1.185 U1.187 U1.188 U1.189 U1.191 U1.192 U1.193 U1.194 U1.198 U1.199 U1.200 U1.201 U1.202 U1.203 U1.204 U1.205 U3.2 U3.9 U3.12 U3.13 U3.14 U3.15 U3.16 U4.1 U4.2 U4.6 U4.7 U4.8 U5.2 U5.5 U6.7 U7.7

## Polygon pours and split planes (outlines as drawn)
GND on Top Layer "Top Layer-GND" (hatched 90Degree grid 20 track 8, remove dead copper, pour order 1000): 1048.23,3165.35 3963.58,3165.35 3963.58,1060.04 1040.35,1060.04 1040.35,3165.35
GND on Bottom Layer "Bottom Layer-GND" (hatched 90Degree grid 20 track 8, remove dead copper, pour order 1001): 1048.23,3161.42 3963.58,3161.42 3963.58,1060.04 1048.23,1060.04
VCCO on PwrPlane (split plane): 3999.9,1034.1 1020.1,1034.1 1020.1,3191.9 3999.9,3191.9
VCCINT on PwrPlane (split plane): 2818.72,2308.91 2818.72,1641.88 2758.72,1581.87 2129.08,1581.87 2099.59,1611.36 2099.59,1796.26 2099.2,1798.21 2098.09,1799.86 2078.41,1819.55 2076.75,1820.65 2074.8,1821.04 1414.55,1821.04 1414.55,1946.67 2068.9,1946.67 2070.85,1947.06 2072.5,1948.17 2093.17,1968.84 2094.28,1970.49 2094.66,1972.44 2094.66,2238.05 2229.47,2372.85 2754.78,2372.85
GND on GndPlane (split plane): 3999.9,1034.1 1020.1,1034.1 1020.1,3191.9 3999.9,3191.9

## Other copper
PwrPlane (plane layer: these items are gaps in the copper):
  lines w10: 1407.48,1817.91 1409.45,1815.94 ; 1409.45,1815.94 2074.8,1815.94 2094.49,1796.26 2094.49,1609.25 2126.97,1576.77 2760.83,1576.77 2823.82,1639.76 2823.82,2311.02 2756.89,2377.95 2227.36,2377.95 2089.57,2240.16 2089.57,1972.44 2068.9,1951.77 1407.48,1951.77 1409.45,1949.8 1409.45,1815.94

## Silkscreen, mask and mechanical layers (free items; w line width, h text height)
Top Overlay:
  text "uP-D" at 3604.33,2669.29 h78.74
Mechanical 1:
  the board outline again, w10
